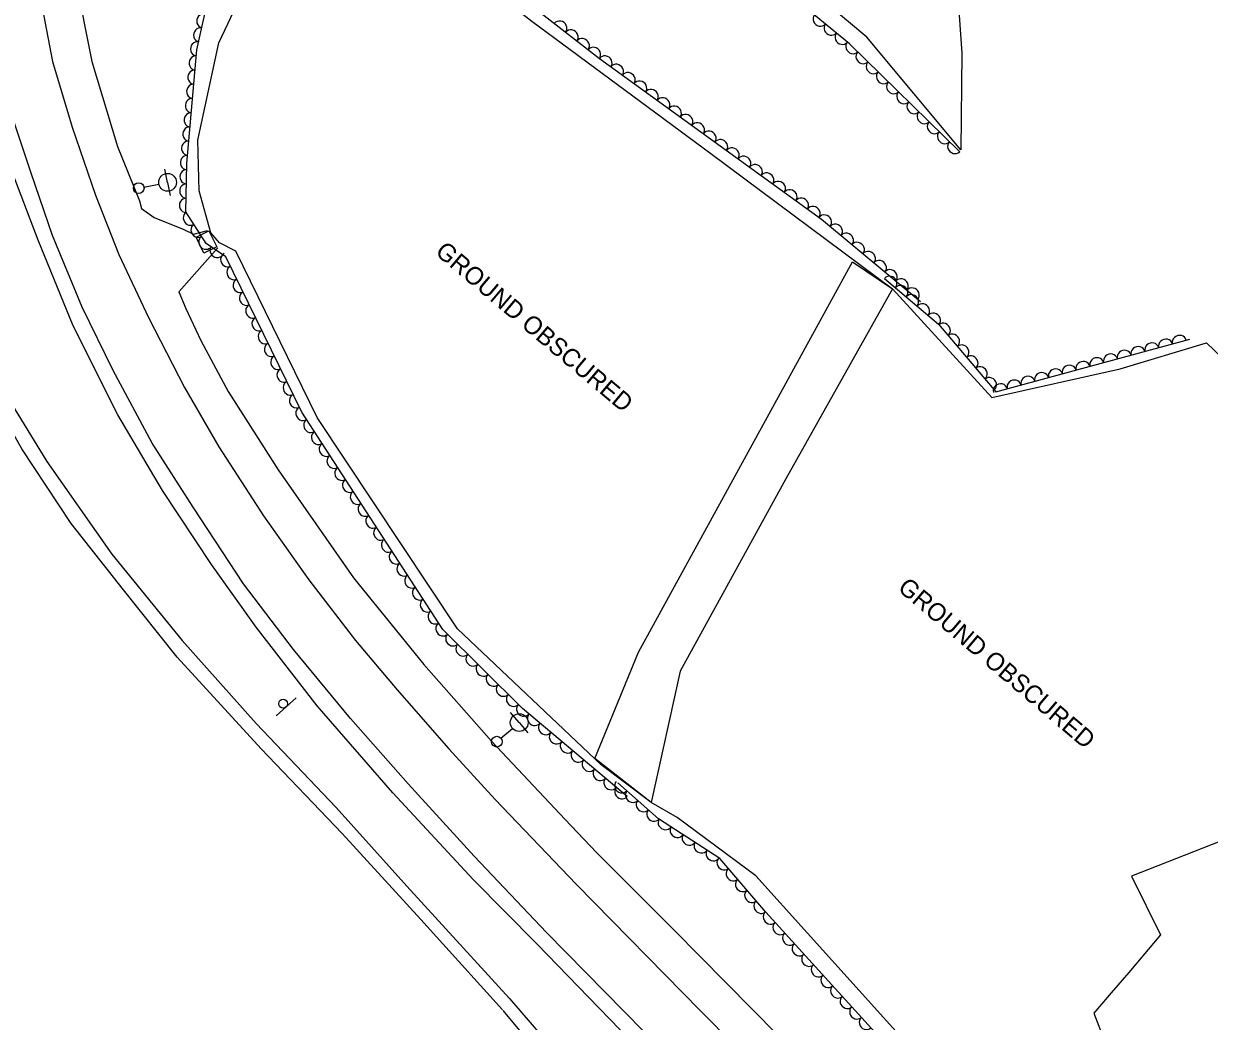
# Model space of a CAD drawing. Extents: x 1722896 to 1754269, y 648279 to 666297.
# Drawn here: x 1730544.3 to 1730876.7, y 652553.4 to 652833.1 of the extents above; entities that cross this region are included whole.
import ezdxf

# ---------------------------------------------------------------- set-up
doc = ezdxf.new("R2010")
doc.units = 0
for name, color, linetype in [('DESIGN - CENTERLINE - Proposed', 7, 'Continuous'), ('DESIGN - PUBLIC HEARING - Shapes', 7, 'Continuous'), ('SURVEY - CENTERLINE - Preliminary', 7, 'Continuous'), ('SURVEY - CENTERLINE - Preliminary Text', 7, 'Continuous'), ('SURVEY - DRAINAGE - Natural Features', 7, 'Continuous'), ('SURVEY - DTM - Breaklines', 7, 'Continuous'), ('SURVEY - VEGETATION - Features with Text', 7, 'Continuous')]:
    doc.layers.add(name, color=color, linetype=linetype)

msp = doc.modelspace()

# ---------------------------------------------------------------- linework, layer by layer
at = {"layer": 'DESIGN - CENTERLINE - Proposed'}
for points in [[(1730678.62, 652556.59), (1730655.66, 652581.98), (1730633.59, 652606.1), (1730610.89, 652629.81), (1730587.34, 652655.47), (1730572.3, 652674.38), (1730557.65, 652692.98), (1730543.82, 652713.96), (1730532.68, 652733.61), (1730519.92, 652760.34), (1730509.3, 652785), (1730512.44, 652786.79), (1730523.91, 652760.51), (1730537.26, 652732.3), (1730550.79, 652710.35), (1730569.07, 652684.4), (1730588.75, 652660.2), (1730609.5, 652636.9), (1730631.92, 652613.32), (1730651.78, 652591.33), (1730680.55, 652559.79)], [(1730680.55, 652559.79), (1730692.7, 652545.7), (1730709.91, 652525.37), (1730718.77, 652514.41), (1730723.95, 652505.3), (1730732.58, 652490.12), (1730745.14, 652472.49), (1730742.29, 652470.74), (1730729.36, 652489.33), (1730716.79, 652509.98), (1730709.15, 652520.66), (1730692.91, 652539.5), (1730678.73, 652556.46)]]:
    msp.add_lwpolyline(points, dxfattribs=at)
at = {"layer": 'DESIGN - PUBLIC HEARING - Shapes'}
msp.add_line((1730620.69, 652644.09), (1730615.14, 652639.04), dxfattribs=at)
msp.add_circle((1730617.07, 652642.45), 1.25, dxfattribs=at)
at = {"layer": 'SURVEY - CENTERLINE - Preliminary'}
for points in [[(1730807.06, 652797.76), (1730780.73, 652829.3), (1730749.9, 652855.19), (1730723.01, 652859.3), (1730688.62, 652856.46), (1730680.37, 652873.54), (1730680.36, 652892.76), (1730681.12, 652919.34), (1730685.44, 652923.8), (1730697.79, 652936.46), (1730713.42, 652961.05), (1730738.2, 652949.22), (1730734.38, 652930.84), (1730751.89, 652921.68), (1730802.97, 652917), (1730804.21, 652870.04), (1730807.32, 652824.85), (1730807.06, 652797.76)], [(1730720.27, 652614.71), (1730706.25, 652625.32), (1730665.93, 652663.44), (1730626.63, 652722.75), (1730603.83, 652769.34), (1730599.26, 652771.7), (1730596.79, 652774.46), (1730593.52, 652786.22), (1730593.19, 652800.47), (1730599.08, 652827.8), (1730610.64, 652852.31), (1730617.3, 652894.86), (1730633.08, 652897.49), (1730650.84, 652893.26), (1730655.08, 652874.49), (1730646.65, 652865.12), (1730686.8, 652833.8), (1730736.98, 652796.74), (1730787.91, 652758.78), (1730758.05, 652705.53), (1730728.4, 652651.58), (1730720.27, 652614.71)], [(1730793.05, 652545.92), (1730749.62, 652594.18), (1730727.57, 652610.51), (1730720.27, 652614.71), (1730704.43, 652627.1), (1730716.71, 652656.92), (1730776.72, 652766.37), (1730787.91, 652758.78), (1730815.81, 652728.35), (1730851.78, 652736.36), (1730875.99, 652743.63), (1730933.46, 652688.6), (1730972.83, 652603.53), (1731025.6, 652490.27)], [(1730908.17, 652545.92), (1730893.45, 652566.1), (1730882.36, 652604.84), (1730854.94, 652594.13), (1730863.06, 652577.64), (1730854.16, 652567.13), (1730849.25, 652561.41), (1730844.36, 652555.66), (1730853.54, 652531.88)]]:
    msp.add_lwpolyline(points, dxfattribs=at)
at = {"layer": 'SURVEY - CENTERLINE - Preliminary Text'}
for points in [[(1730690.91, 652578.28), (1730670.64, 652599.73), (1730652.08, 652619.98), (1730635.95, 652638.35), (1730620.02, 652657.68), (1730605.98, 652676.11), (1730591.81, 652697.52), (1730580.39, 652715.47), (1730569.39, 652735.86), (1730560.76, 652753.62), (1730552.41, 652773.72), (1730546.42, 652791.17), (1730540.93, 652807.79), (1730537, 652822.62), (1730534.28, 652835.9), (1730531.95, 652852.41), (1730530.87, 652867.87), (1730530.75, 652886.96), (1730532.31, 652912.93), (1730536.34, 652936.8)], [(1730546.39, 652905.08), (1730545.42, 652881.65), (1730546.16, 652863.31), (1730548.63, 652842.14), (1730552.44, 652822.52), (1730557.9, 652804.09), (1730564.49, 652785.05), (1730570.99, 652768.37), (1730579.3, 652750.76), (1730589.44, 652731.15), (1730599.06, 652714.52), (1730611.56, 652695.09), (1730624.29, 652677.22), (1730637.32, 652660.18), (1730649.06, 652646.37), (1730663.49, 652629.81), (1730676.52, 652615.58), (1730699.27, 652591.88)], [(1730688.22, 652575.09), (1730670.36, 652593.21), (1730647.86, 652617.46), (1730626.59, 652641.84), (1730609.48, 652663.96), (1730596.97, 652681.47), (1730583.23, 652702.24), (1730570.75, 652723.48), (1730558.17, 652748.44), (1730548.35, 652772.38), (1730540.62, 652792.8), (1730534.01, 652815.65), (1730529.83, 652835.2), (1730527.59, 652852.49), (1730525.28, 652875.17), (1730525.91, 652885.34)], [(1730555.7, 652884.68), (1730556.86, 652868.28), (1730558.74, 652846.08), (1730563.39, 652822.51), (1730570.59, 652798.7), (1730576.75, 652783.49), (1730577.39, 652781.33), (1730580.93, 652778.79), (1730589.05, 652775.53), (1730591.95, 652774.13), (1730595.86, 652775.17)], [(1730598.72, 652770.28), (1730587.83, 652757.91), (1730589.81, 652753.23), (1730594.01, 652744.33), (1730601.62, 652729.98), (1730615.63, 652708.03), (1730636.79, 652677.72), (1730656.53, 652653.41), (1730675.5, 652631.98), (1730696.1, 652609.95), (1730704.92, 652600.69)], [(1731169.96, 652134.42), (1731125.44, 652179.48), (1731078.79, 652226.64), (1731045.15, 652259.85), (1731035.13, 652270.28), (1731037.86, 652291.12), (1731039.55, 652293.11), (1731035.46, 652296.58), (1731033.59, 652294.84), (1731015.17, 652296.23), (1731007.12, 652298.48), (1730978.29, 652326.95), (1730936.8, 652368.15), (1730888.87, 652415.83), (1730846.66, 652458.3), (1730801.1, 652503.68), (1730763.06, 652542.15), (1730726.59, 652579.08), (1730704.92, 652600.69)], [(1730699.27, 652591.88), (1730734.05, 652556.32), (1730771.95, 652518.16), (1730809.27, 652481.29), (1730849.67, 652440.74), (1730899.23, 652391.25), (1730945.2, 652344.86), (1730992.78, 652297.53), (1731029.17, 652261.39), (1731063.45, 652227.26), (1731109.02, 652181.07), (1731162.34, 652127.31)], [(1731077.97, 652191.36), (1731038.58, 652230.31), (1730995.88, 652272.95), (1730942.44, 652326.59), (1730913.71, 652354.92), (1730877.51, 652391.02), (1730836.99, 652431.73), (1730798.41, 652470.26), (1730756.63, 652512.07), (1730718.21, 652550.58), (1730690.91, 652578.28)], [(1730688.22, 652575.09), (1730723.14, 652539.09)]]:
    msp.add_lwpolyline(points, dxfattribs=at)
at = {"layer": 'SURVEY - DRAINAGE - Natural Features'}
msp.add_line((1730595.54, 652771.92), (1730595.54, 652771.92), dxfattribs=at)
msp.add_lwpolyline([(1730592.64, 652773.28), (1730596.23, 652775.05), (1730598.44, 652770.56), (1730594.86, 652768.79), (1730592.64, 652773.28)], dxfattribs=at)
at = {"layer": 'SURVEY - DTM - Breaklines'}
for p, q in [((1730584.67, 652788.64), (1730583.94, 652792.32)), ((1730578.05, 652787.33), (1730582.21, 652788.15)), ((1730584.67, 652788.64), (1730585.4, 652784.96)), ((1730683.27, 652637.16), (1730680.83, 652640.02)), ((1730683.27, 652637.16), (1730685.7, 652634.31)), ((1730678.13, 652632.79), (1730681.36, 652635.54))]:
    msp.add_line(p, q, dxfattribs=at)
for centre, radius in [((1730584.67, 652788.64), 2.5), ((1730576.57, 652787.03), 1.5), ((1730683.27, 652637.16), 2.5), ((1730676.99, 652631.81), 1.5)]:
    msp.add_circle(centre, radius, dxfattribs=at)
at = {"layer": 'SURVEY - VEGETATION - Features with Text'}
for points in [[(1730806.76, 652797.22), (1730775.89, 652827.5), (1730747.7, 652850.65), (1730721.78, 652853.91), (1730689.85, 652851.64), (1730676.75, 652871.66), (1730672.12, 652906.71), (1730676.85, 652921.56), (1730695.74, 652944.96), (1730712.19, 652965.82), (1730741.98, 652952.8), (1730739.22, 652930.27), (1730748.05, 652924.04), (1730806.81, 652920.55)], [(1730713.54, 652616.39), (1730684.15, 652641.11), (1730661.89, 652663.27), (1730622.32, 652724.18), (1730601.02, 652767.77), (1730595.5, 652771.51), (1730589.82, 652780.37), (1730590.1, 652793.94), (1730592.91, 652825.76), (1730599.98, 652857.72), (1730608.67, 652886.97), (1730619.32, 652903), (1730637.28, 652909.47), (1730651.84, 652903.97), (1730659.15, 652892.81), (1730659.64, 652879.72), (1730657.92, 652870.22), (1730654.14, 652863.51), (1730705.73, 652823.35), (1730767.98, 652778.32), (1730795.73, 652755.25)], [(1730785.69, 652761.68), (1730800.78, 652748.91), (1730816.87, 652729.92), (1730871.31, 652744.64)], [(1731157.42, 652195.95), (1731114.13, 652249.62), (1731095.48, 652233.42), (1731066.26, 652265.59), (1731023.15, 652311.69), (1731014.5, 652317.12), (1731006.79, 652316.74), (1730997.26, 652323.24), (1730990.99, 652332.4), (1730987.09, 652344.57), (1730986.4, 652345.65), (1730951.78, 652380.69), (1730912.44, 652417.78), (1730885.63, 652446.22), (1730866.29, 652472.09), (1730836.36, 652497.88), (1730819.66, 652514.78), (1730798.55, 652537.6), (1730785.8, 652547.24), (1730752.38, 652583.97), (1730739.54, 652599.07), (1730722.36, 652610.22), (1730710.94, 652620.28)]]:
    msp.add_lwpolyline(points, dxfattribs=at)
for centre, major_axis in [((1730594.71, 652833.89), (0.43, 1.95)), ((1730694.68, 652831.95), (1.58, -1.23)), ((1730767.58, 652834.33), (-1.55, 1.27)), ((1730770.67, 652831.79), (-1.55, 1.27)), ((1730593.84, 652829.98), (0.43, 1.95)), ((1730697.84, 652829.49), (1.58, -1.23)), ((1730773.76, 652829.25), (-1.55, 1.27)), ((1730592.98, 652826.07), (0.43, 1.95)), ((1730700.99, 652827.03), (1.58, -1.23)), ((1730704.15, 652824.58), (1.58, -1.23)), ((1730776.78, 652826.63), (-1.43, 1.4)), ((1730592.58, 652822.1), (0.18, 1.99)), ((1730707.35, 652822.18), (1.62, -1.17)), ((1730779.63, 652823.83), (-1.43, 1.4)), ((1730592.23, 652818.11), (0.18, 1.99)), ((1730710.59, 652819.83), (1.62, -1.17)), ((1730713.83, 652817.49), (1.62, -1.17)), ((1730782.49, 652821.03), (-1.43, 1.4)), ((1730785.34, 652818.23), (-1.43, 1.4)), ((1730591.88, 652814.13), (0.18, 1.99)), ((1730717.07, 652815.14), (1.62, -1.17)), ((1730788.2, 652815.43), (-1.43, 1.4)), ((1730720.31, 652812.8), (1.62, -1.17)), ((1730791.05, 652812.63), (-1.43, 1.4)), ((1730591.53, 652810.14), (0.18, 1.99)), ((1730723.55, 652810.45), (1.62, -1.17)), ((1730726.79, 652808.11), (1.62, -1.17)), ((1730793.91, 652809.82), (-1.43, 1.4)), ((1730591.18, 652806.16), (0.18, 1.99)), ((1730730.03, 652805.77), (1.62, -1.17)), ((1730796.77, 652807.02), (-1.43, 1.4)), ((1730590.83, 652802.17), (0.18, 1.99)), ((1730733.27, 652803.42), (1.62, -1.17)), ((1730736.52, 652801.08), (1.62, -1.17)), ((1730799.62, 652804.22), (-1.43, 1.4)), ((1730802.48, 652801.42), (-1.43, 1.4)), ((1730590.47, 652798.19), (0.18, 1.99)), ((1730739.76, 652798.73), (1.62, -1.17)), ((1730805.33, 652798.62), (-1.43, 1.4)), ((1730590.12, 652794.2), (0.18, 1.99)), ((1730743, 652796.39), (1.62, -1.17)), ((1730746.24, 652794.04), (1.62, -1.17)), ((1730749.48, 652791.7), (1.62, -1.17)), ((1730590.02, 652790.21), (0.04, 2)), ((1730752.72, 652789.36), (1.62, -1.17)), ((1730589.94, 652786.21), (0.04, 2)), ((1730755.96, 652787.01), (1.62, -1.17)), ((1730759.2, 652784.67), (1.62, -1.17)), ((1730589.86, 652782.21), (0.04, 2)), ((1730762.44, 652782.32), (1.62, -1.17)), ((1730590.99, 652778.55), (-1.08, 1.68)), ((1730765.69, 652779.98), (1.62, -1.17)), ((1730768.88, 652777.57), (1.54, -1.28)), ((1730593.14, 652775.18), (-1.08, 1.68)), ((1730771.95, 652775.01), (1.54, -1.28)), ((1730595.3, 652771.82), (-1.08, 1.68)), ((1730775.03, 652772.46), (1.54, -1.28)), ((1730598.51, 652769.47), (-1.66, 1.12)), ((1730778.11, 652769.9), (1.54, -1.28)), ((1730781.18, 652767.34), (1.54, -1.28)), ((1730601.45, 652766.9), (-0.88, 1.8)), ((1730784.26, 652764.79), (1.54, -1.28)), ((1730603.2, 652763.31), (-0.88, 1.8)), ((1730787.33, 652762.23), (1.54, -1.28)), ((1730604.96, 652759.71), (-0.88, 1.8)), ((1730787.22, 652760.39), (1.53, -1.29)), ((1730790.27, 652757.8), (1.53, -1.29)), ((1730790.41, 652759.67), (1.54, -1.28)), ((1730606.71, 652756.12), (-0.88, 1.8)), ((1730793.32, 652755.22), (1.53, -1.29)), ((1730793.48, 652757.11), (1.54, -1.28)), ((1730608.47, 652752.53), (-0.88, 1.8)), ((1730796.38, 652752.64), (1.53, -1.29)), ((1730610.23, 652748.93), (-0.88, 1.8)), ((1730799.43, 652750.05), (1.53, -1.29)), ((1730611.98, 652745.34), (-0.88, 1.8)), ((1730802.22, 652747.21), (1.29, -1.53)), ((1730804.81, 652744.15), (1.29, -1.53)), ((1730613.74, 652741.74), (-0.88, 1.8)), ((1730807.4, 652741.1), (1.29, -1.53)), ((1730860.65, 652741.76), (1.93, 0.52)), ((1730864.51, 652742.8), (1.93, 0.52)), ((1730868.37, 652743.84), (1.93, 0.52)), ((1730615.49, 652738.15), (-0.88, 1.8)), ((1730809.98, 652738.05), (1.29, -1.53)), ((1730845.2, 652737.58), (1.93, 0.52)), ((1730849.06, 652738.63), (1.93, 0.52)), ((1730852.92, 652739.67), (1.93, 0.52)), ((1730856.78, 652740.71), (1.93, 0.52)), ((1730617.25, 652734.55), (-0.88, 1.8)), ((1730812.57, 652735), (1.29, -1.53)), ((1730833.62, 652734.45), (1.93, 0.52)), ((1730837.48, 652735.49), (1.93, 0.52)), ((1730841.34, 652736.54), (1.93, 0.52)), ((1730815.16, 652731.95), (1.29, -1.53)), ((1730822.03, 652731.32), (1.93, 0.52)), ((1730825.89, 652732.36), (1.93, 0.52)), ((1730829.75, 652733.41), (1.93, 0.52)), ((1730619, 652730.96), (-0.88, 1.8)), ((1730818.17, 652730.27), (1.93, 0.52)), ((1730620.76, 652727.37), (-0.88, 1.8)), ((1730622.56, 652723.8), (-1.09, 1.68)), ((1730624.74, 652720.44), (-1.09, 1.68)), ((1730626.92, 652717.09), (-1.09, 1.68)), ((1730629.1, 652713.74), (-1.09, 1.68)), ((1730631.28, 652710.38), (-1.09, 1.68)), ((1730633.46, 652707.03), (-1.09, 1.68)), ((1730635.64, 652703.67), (-1.09, 1.68)), ((1730637.82, 652700.32), (-1.09, 1.68)), ((1730640, 652696.97), (-1.09, 1.68)), ((1730642.18, 652693.61), (-1.09, 1.68)), ((1730644.36, 652690.26), (-1.09, 1.68)), ((1730646.53, 652686.9), (-1.09, 1.68)), ((1730648.71, 652683.55), (-1.09, 1.68)), ((1730650.89, 652680.19), (-1.09, 1.68)), ((1730653.07, 652676.84), (-1.09, 1.68)), ((1730655.25, 652673.49), (-1.09, 1.68)), ((1730657.43, 652670.13), (-1.09, 1.68)), ((1730659.61, 652666.78), (-1.09, 1.68)), ((1730661.79, 652663.42), (-1.09, 1.68)), ((1730664.59, 652660.58), (-1.42, 1.41)), ((1730667.43, 652657.76), (-1.42, 1.41)), ((1730670.26, 652654.93), (-1.42, 1.41)), ((1730673.1, 652652.11), (-1.42, 1.41)), ((1730675.93, 652649.29), (-1.42, 1.41)), ((1730678.77, 652646.47), (-1.42, 1.41)), ((1730681.6, 652643.64), (-1.42, 1.41)), ((1730684.46, 652640.85), (-1.53, 1.29)), ((1730687.52, 652638.27), (-1.53, 1.29)), ((1730690.58, 652635.7), (-1.53, 1.29)), ((1730693.64, 652633.12), (-1.53, 1.29)), ((1730696.71, 652630.55), (-1.53, 1.29)), ((1730699.77, 652627.98), (-1.53, 1.29)), ((1730702.83, 652625.4), (-1.53, 1.29)), ((1730705.89, 652622.83), (-1.53, 1.29)), ((1730708.95, 652620.25), (-1.53, 1.29)), ((1730711.98, 652619.36), (-1.5, 1.32)), ((1730712.01, 652617.68), (-1.53, 1.29)), ((1730714.98, 652616.72), (-1.5, 1.32)), ((1730717.98, 652614.08), (-1.5, 1.32)), ((1730720.98, 652611.43), (-1.5, 1.32)), ((1730724.17, 652609.04), (-1.68, 1.09)), ((1730727.53, 652606.86), (-1.68, 1.09)), ((1730730.89, 652604.69), (-1.68, 1.09)), ((1730734.24, 652602.51), (-1.68, 1.09)), ((1730737.6, 652600.33), (-1.68, 1.09)), ((1730740.63, 652597.79), (-1.3, 1.52)), ((1730743.22, 652594.74), (-1.3, 1.52)), ((1730745.81, 652591.7), (-1.3, 1.52)), ((1730748.4, 652588.65), (-1.3, 1.52)), ((1730750.99, 652585.6), (-1.3, 1.52)), ((1730753.63, 652582.59), (-1.35, 1.48)), ((1730756.32, 652579.64), (-1.35, 1.48)), ((1730759.02, 652576.68), (-1.35, 1.48)), ((1730761.71, 652573.72), (-1.35, 1.48)), ((1730764.4, 652570.76), (-1.35, 1.48)), ((1730767.09, 652567.8), (-1.35, 1.48)), ((1730769.79, 652564.84), (-1.35, 1.48)), ((1730772.48, 652561.88), (-1.35, 1.48)), ((1730775.17, 652558.93), (-1.35, 1.48)), ((1730777.86, 652555.97), (-1.35, 1.48)), ((1730780.55, 652553.01), (-1.35, 1.48))]:
    msp.add_ellipse(centre, major_axis=major_axis, ratio=0.940188, start_param=0, end_param=3.141593, dxfattribs=at)

# ---------------------------------------------------------------- texts
at = {"layer": 'SURVEY - CENTERLINE - Preliminary'}
for rotation, p in [(319.8381, (1730659.42, 652768.67)), (319.6763, (1730789.1, 652674.44))]:
    msp.add_text('GROUND OBSCURED', height=5, rotation=rotation, dxfattribs=at).set_placement(p)

doc.saveas('drawing.dxf')
